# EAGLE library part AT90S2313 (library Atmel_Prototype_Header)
8-bit AVR Microcontroller with 2K bytes In-System Programmable Flash
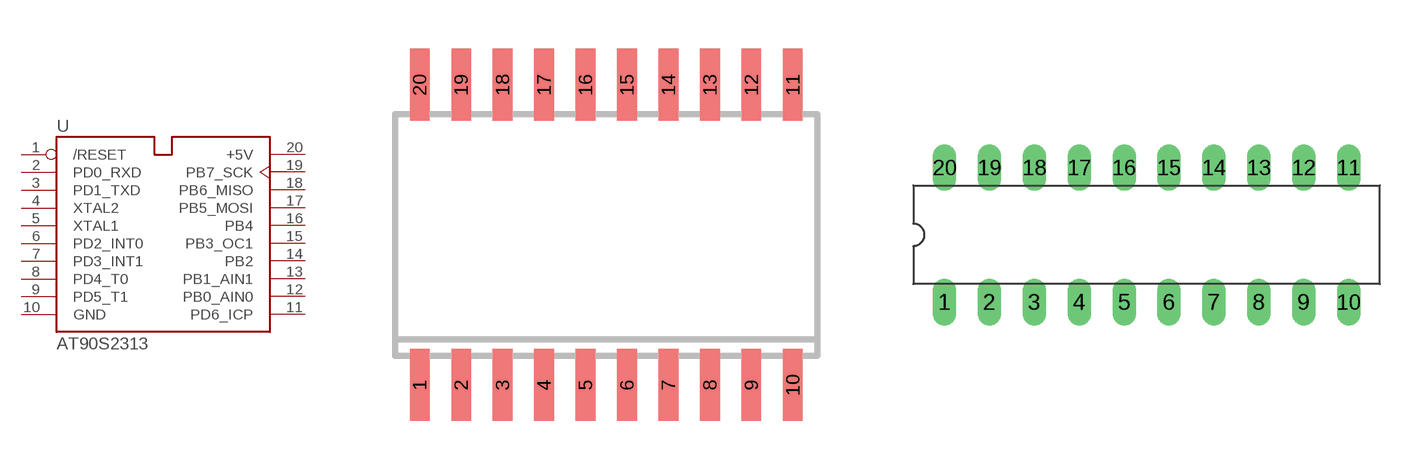
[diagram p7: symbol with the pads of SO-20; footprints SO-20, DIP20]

Designator prefix U

## AT90S2313_SO-20  [SO-20]
1  /RESET  in
2  PD0_RXD  in
3  PD1_TXD  out
4  XTAL2
5  XTAL1
6  PD2_INT0
7  PD3_INT1
8  PD4_T0
9  PD5_T1
10  GND  pwr
11  PD6_ICP
12  PB0_AIN0
13  PB1_AIN1
14  PB2
15  PB3_OC1
16  PB4
17  PB5_MOSI
18  PB6_MISO
19  PB7_SCK
20  +5V  pwr

## AT90S2313_DIP20  [DIP20]
Pads as for SO-20

## Footprint SO-20 (pad centres in mm)
smd 0.6 x 2.2: 1 -5.715,-4.6; 2 -4.445,-4.6; 3 -3.175,-4.6; 4 -1.905,-4.6; 5 -0.635,-4.6; 6 0.635,-4.6; 7 1.905,-4.6; 8 3.175,-4.6; 9 4.445,-4.6; 10 5.715,-4.6; 11 5.715,4.6; 12 4.445,4.6; 13 3.175,4.6; 14 1.905,4.6; 15 0.635,4.6; 16 -0.635,4.6; 17 -1.905,4.6; 18 -3.175,4.6; 19 -4.445,4.6; 20 -5.715,4.6

## Footprint DIP20 (pad centres in mm)
drill 0.813 long: 1 -11.43,-3.81; 2 -8.89,-3.81; 3 -6.35,-3.81; 4 -3.81,-3.81; 5 -1.27,-3.81; 6 1.27,-3.81; 7 3.81,-3.81; 8 6.35,-3.81; 9 8.89,-3.81; 10 11.43,-3.81; 11 11.43,3.81; 12 8.89,3.81; 13 6.35,3.81; 14 3.81,3.81; 15 1.27,3.81; 16 -1.27,3.81; 17 -3.81,3.81; 18 -6.35,3.81; 19 -8.89,3.81; 20 -11.43,3.81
